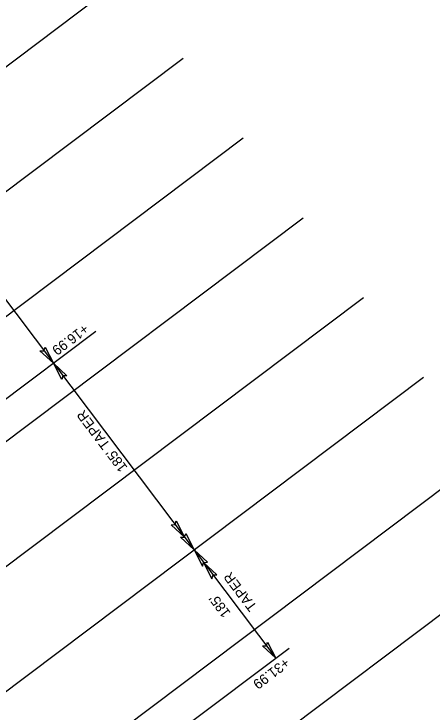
# Model space of a CAD drawing. Extents: x 1262309 to 1264352, y 775189 to 777755.
# Drawn here: x 1263797 to 1264006.1, y 776188.9 to 776538.6 of the extents above; entities that cross this region are included whole.
import ezdxf

# ---------------------------------------------------------------- set-up
doc = ezdxf.new("R2010")
doc.units = 0
for name, color, linetype in [('Prop Dimension', 7, 'Continuous'), ('Prop Dimension Text', 7, 'Continuous'), ('Scratch_Level_3', 7, 'Continuous')]:
    doc.layers.add(name, color=color, linetype=linetype)

msp = doc.modelspace()

# ---------------------------------------------------------------- linework, layer by layer
at = {"layer": 'Prop Dimension'}
for p, q in [((1263606.13, 776643.21), (1263816.71, 776363.63)), ((1263837.89, 776379.6), (1263727.72, 776296.6)), ((1263816.71, 776363.63), (1263928, 776215.87)), ((1263934.61, 776220.85), (1263761.55, 776090.5))]:
    msp.add_line(p, q, dxfattribs=at)
at = {"layer": 'Prop Dimension Text'}
for points in [[(1263812.52, 776371.76), (1263816.7, 776363.64), (1263809.98, 776369.91), (1263811.95, 776369.95)], [(1263820.88, 776355.52), (1263816.7, 776363.64), (1263823.42, 776357.37), (1263821.45, 776357.33)], [(1263878.14, 776284.65), (1263882.32, 776276.52), (1263875.6, 776282.79), (1263877.57, 776282.83)], [(1263882.89, 776278.33), (1263887.07, 776270.21), (1263880.35, 776276.48), (1263882.32, 776276.52)], [(1263893.72, 776263.96), (1263887.07, 776270.21), (1263891.24, 776262.02), (1263891.82, 776263.9)], [(1263898.48, 776257.65), (1263891.82, 776263.9), (1263895.99, 776255.71), (1263896.58, 776257.59)], [(1263923.83, 776223.99), (1263928, 776215.87), (1263921.28, 776222.14), (1263923.25, 776222.18)]]:
    msp.add_lwpolyline(points, close=True, dxfattribs=at)
at = {"layer": 'Scratch_Level_3'}
for p, q in [((1263356.4, 776183.46), (1263851.5, 776556.37)), ((1263386.48, 776143.52), (1263881.58, 776516.43)), ((1263416.56, 776103.58), (1263911.66, 776476.49)), ((1263446.64, 776063.64), (1263941.74, 776436.56)), ((1263476.73, 776023.7), (1263971.83, 776396.62)), ((1263506.81, 775983.76), (1264001.91, 776356.68)), ((1263536.89, 775943.83), (1264031.99, 776316.74)), ((1263566.97, 775903.89), (1264062.07, 776276.8))]:
    msp.add_line(p, q, dxfattribs=at)

# ---------------------------------------------------------------- texts
at = {"layer": 'Prop Dimension Text'}
for s, rotation, p in [('+16.99', 216.9874, (1263832.02, 776383.66)), ("185' TAPER", 126.9874, (1263853.98, 776311.49)), ('TAPER', 126.9874, (1263918.87, 776241.77)), ("185'", 126.9874, (1263905.6, 776238.62)), ('+31.99', 216.9874, (1263932.58, 776216.4))]:
    msp.add_text(s, height=5, rotation=rotation, dxfattribs=at).set_placement(p)

doc.saveas('drawing.dxf')
